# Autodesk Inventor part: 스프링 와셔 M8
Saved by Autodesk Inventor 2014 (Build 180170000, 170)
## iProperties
Created: 2025-10
Part Number: 스프링 와셔 M8
Material: 일반
Document SubType Name: Modeling
Designer: dg
Density: 1 g/cm^3
Appearance: 기본값
Author: dg
Author: jhkim
Description: 스프링 잠금 와셔
Creation Date: 2025-10-01
Sending System: Autodesk Inventor 2026
Preprocessor: ST-DEVELOPER v20.1
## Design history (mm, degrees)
node "스프링 와셔 M81"
body "Solid1"
node "기준1"
